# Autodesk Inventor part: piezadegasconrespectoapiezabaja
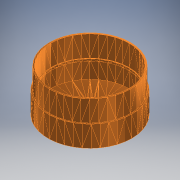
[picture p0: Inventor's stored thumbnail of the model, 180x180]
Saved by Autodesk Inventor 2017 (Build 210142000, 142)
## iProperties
Part Number: piezadegasconrespectoapiezabaja
Material: Oro
Document SubType Name: Modeling
Designer: Yavhee
Density: 19.3 g/cm^3
Appearance: Canario
Author: Yavhee
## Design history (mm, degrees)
node "piezadegasconrespectoapiezabaja"
  node "MeshFeature1"
